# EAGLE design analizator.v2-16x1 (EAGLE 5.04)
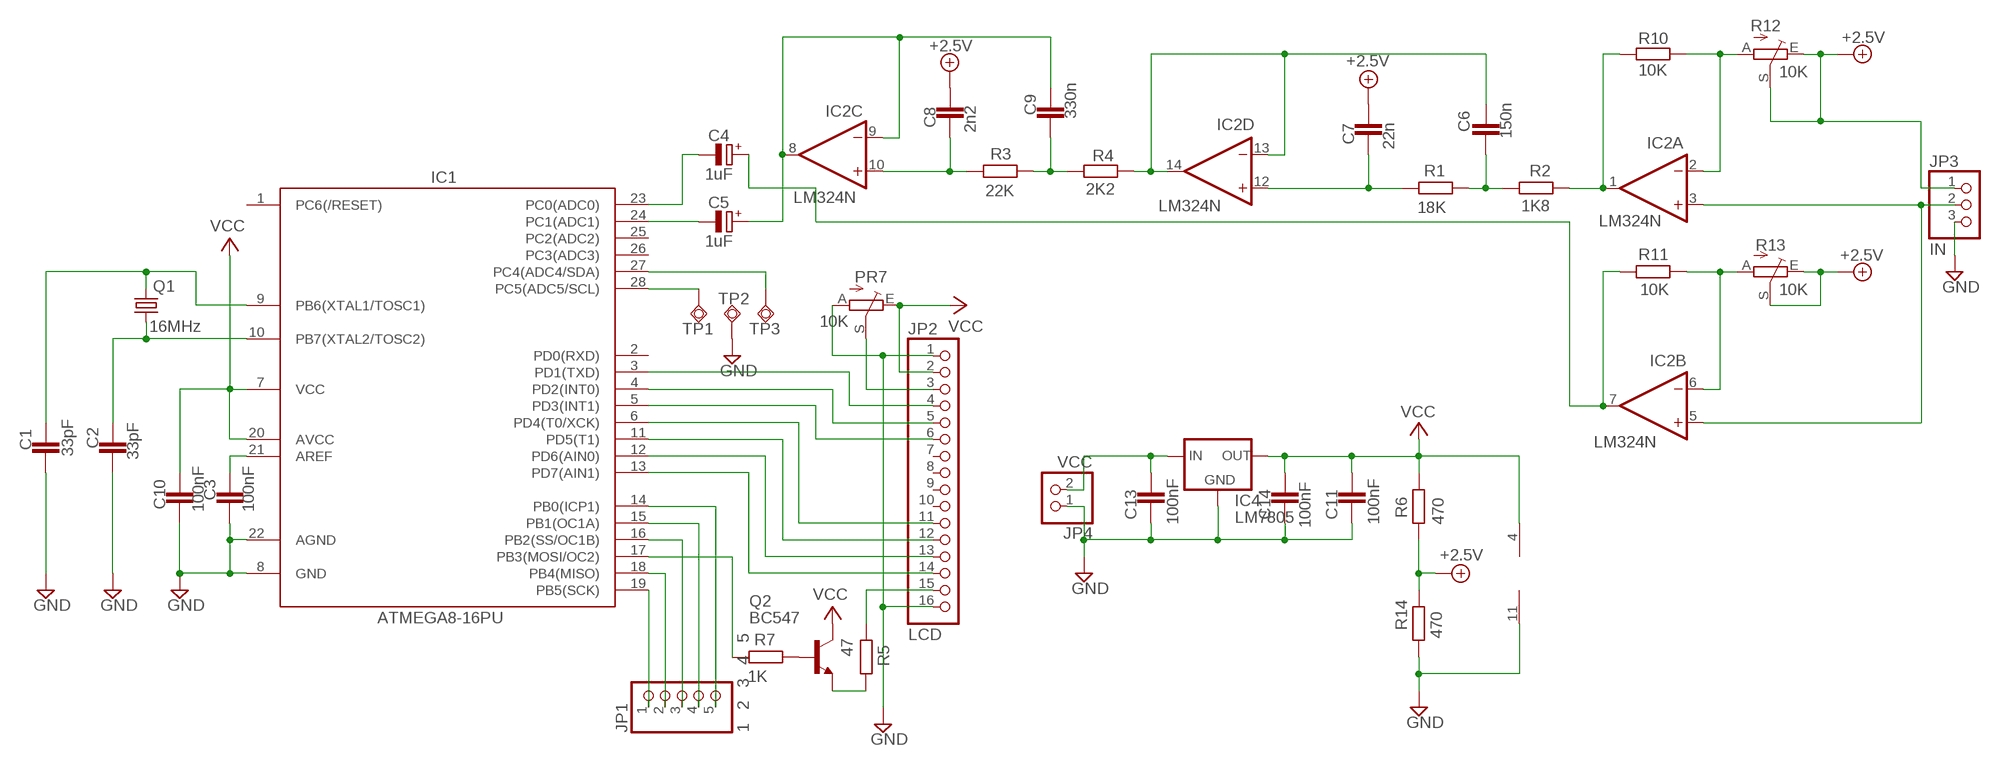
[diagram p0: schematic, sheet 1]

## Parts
C1  33pF  C-EU025-024X044  [C025-024X044]
C2  33pF  C-EU025-024X044  [C025-024X044]
C3  100nF  C-EU050-025X075  [C050-025X075]
C4  1uF  CPOL-EUE5-4  [E5-4]
C5  1uF  CPOL-EUE5-4  [E5-4]
C6  150n  C-EU050-025X075  [C050-025X075]
C7  22n  C-EU050-025X075  [C050-025X075]
C8  2n2  C-EU050-025X075  [C050-025X075]
C9  330n  C-EU050-025X075  [C050-025X075]
C10  100nF  C-EU050-025X075  [C050-025X075]
C11  100nF  C-EU050-025X075  [C050-025X075]
C13  100nF  C-EU050-025X075  [C050-025X075]
C14  100nF  C-EU050-025X075  [C050-025X075]
IC1  ATMEGA8-16PU  ATMEGA8-PU  [DIL28-3]
IC2  LM324N  [DIL14]
IC4  LM7805  78XXL  [78XXL]
JP1  1 2 3 4 5  PINHD-1X5  [1X05]
JP2  LCD  PINHD-1X16  [1X16]
JP3  IN  PINHD-1X3  [1X03]
JP4  VCC  PINHD-1X2  [1X02]
PR7  10K  TRIM_EU-CA6V  [CA6V]
Q1  16MHz  CRYTALHC49S  [HC49/S]
Q2  BC547  [TO92]
R1  18K  R-EU_0204/7  [0204/7]
R2  1K8  R-EU_0204/7  [0204/7]
R3  22K  R-EU_0204/7  [0204/7]
R4  2K2  R-EU_0204/7  [0204/7]
R5  47  R-EU_0204/7  [0204/7]
R6  470  R-EU_0204/7  [0204/7]
R7  1K  R-EU_0204/7  [0204/7]
R10  10K  R-EU_0204/7  [0204/7]
R11  10K  R-EU_0204/7  [0204/7]
R12  10K  TRIM_EU-CA6V  [CA6V]
R13  10K  TRIM_EU-CA6V  [CA6V]
R14  470  R-EU_0204/7  [0204/7]
TP1  TPSQTP11SQ  [TP11SQ]
TP2  TPSQTP11SQ  [TP11SQ]
TP3  TPSQTP11SQ  [TP11SQ]

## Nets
+5V: C7.1 C8.1 JP3.1 R6.1 R12.E R12.S R13.E R13.S R14.2 ; supply symbol labelled +2.5V
GND: C1.1 C2.1 C3.1 C10.1 C11.2 C13.2 C14.2 IC1.8(GND) IC1.22(AGND) IC2.11(P:V-) IC4.GND JP2.1 JP2.16 JP3.3 JP4.1 PR7.A R14.1 TP2.TP
N$1: C1.2 IC1.9(PB6(XTAL1/TOSC1)) Q1.2
N$2: C2.2 IC1.10(PB7(XTAL2/TOSC2)) Q1.1
N$3: C4.- IC1.23(PC0(ADC0))
N$4: C3.2 IC1.21(AREF)
N$5: C5.- IC1.24(PC1(ADC1))
N$6: C6.2 IC2.13(D:-IN) IC2.14(D:OUT) R4.2
N$7: C5.+ C9.2 IC2.8(C:OUT) IC2.9(C:-IN)
N$8: JP2.3 PR7.S
N$9: C7.2 IC2.12(D:+IN) R1.1
N$10: C6.1 R1.2 R2.1
N$11: IC1.3(PD1(TXD)) JP2.4
N$12: C8.2 IC2.10(C:+IN) R3.1
N$13: C9.1 R3.2 R4.1
N$14: IC1.4(PD2(INT0)) JP2.5
N$15: IC2.2(A:-IN) R10.2 R12.A
N$16: IC2.6(B:-IN) R11.2 R13.A
N$17: IC1.5(PD3(INT1)) JP2.6
N$18: IC1.6(PD4(T0/XCK)) JP2.11
N$19: IC1.11(PD5(T1)) JP2.12
N$20: IC1.12(PD6(AIN0)) JP2.13
N$21: IC1.13(PD7(AIN1)) JP2.14
N$22: IC1.17(PB3(MOSI/OC2)) R7.1
N$23: Q2.1(E) R5.2
N$24: IC2.3(A:+IN) IC2.5(B:+IN) JP3.2
N$25: Q2.2(B) R7.2
N$26: IC2.1(A:OUT) R2.2 R10.1
N$27: C4.+ IC2.7(B:OUT) R11.1
N$28: IC1.19(PB5(SCK)) JP1.1
N$29: JP2.15 R5.1
N$30: IC1.18(PB4(MISO)) JP1.2
N$31: IC1.16(PB2(SS/OC1B)) JP1.3
N$32: IC1.15(PB1(OC1A)) JP1.4
N$33: IC1.28(PC5(ADC5/SCL)) TP1.TP
N$38: IC1.14(PB0(ICP1)) JP1.5
N$39: IC1.27(PC4(ADC4/SDA)) TP3.TP
NS$28: C13.1 IC4.IN JP4.2
VCC: C10.2 C11.1 C14.1 IC1.7(VCC) IC1.20(AVCC) IC2.4(P:V+) IC4.OUT JP2.2 PR7.E Q2.3(C) R6.2
Unconnected: IC1.1(PC6(/RESET)) IC1.2(PD0(RXD)) IC1.25(PC2(ADC2)) IC1.26(PC3(ADC3)) JP2.7 JP2.8 JP2.9 JP2.10

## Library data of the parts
C1-C3 C6-C11 C13 C14 = rcl:C-EU: CAPACITOR, European symbol
C4 C5 = rcl:CPOL-EU: POLARIZED CAPACITOR, European symbol
IC1 = atmega8:ATMEGA8-PU
IC2 = linear:LM324: OP AMP
IC4 = v-reg:78XXL: VOLTAGE REGULATOR
JP1 = pinhead:PINHD-1X5: PIN HEADER
JP2 = pinhead:PINHD-1X16: PIN HEADER
JP3 = pinhead:PINHD-1X3: PIN HEADER
JP4 = pinhead:PINHD-1X2: PIN HEADER
PR7 R12 R13 = pot:TRIM_EU-: POTENTIOMETER
Q1 = crystal:CRYTAL: CRYSTAL
Q2 = transistor-npn:BC547*: NPN Transistor
R1-R7 R10 R11 R14 = rcl:R-EU_: RESISTOR, European symbol
TP1-TP3 = testpad:TPSQ

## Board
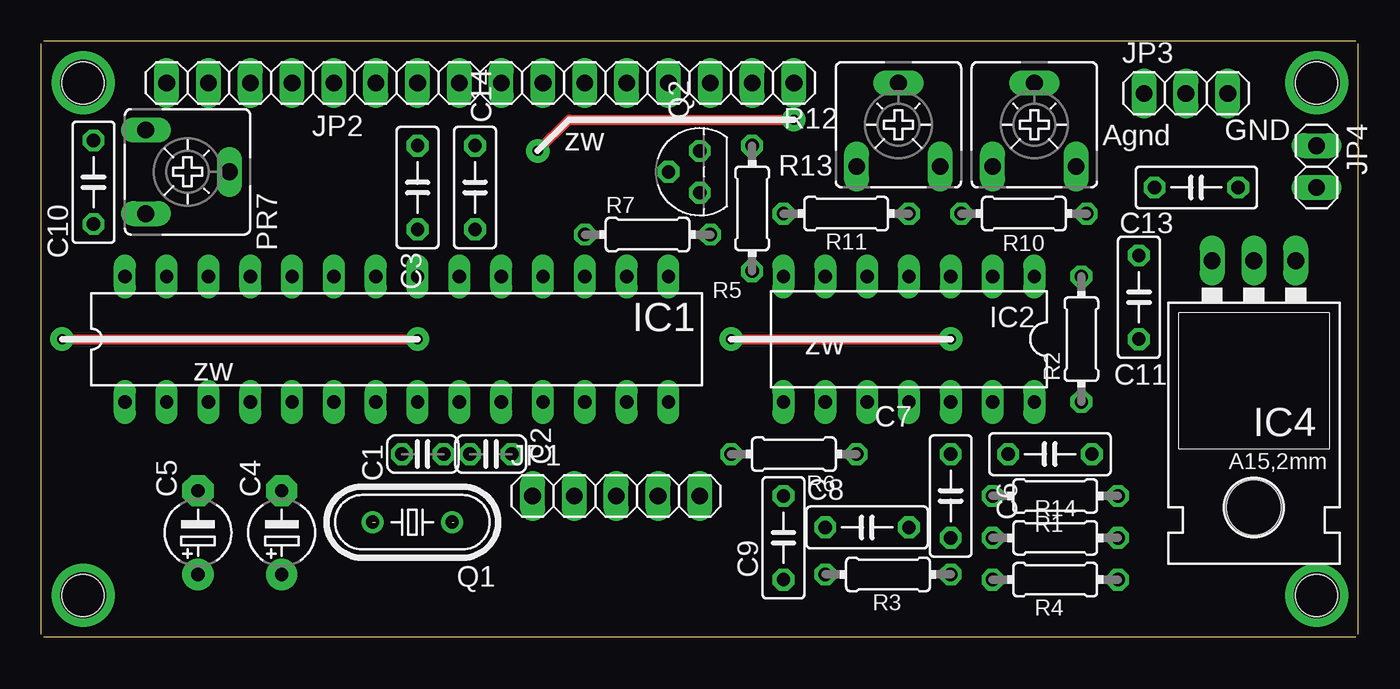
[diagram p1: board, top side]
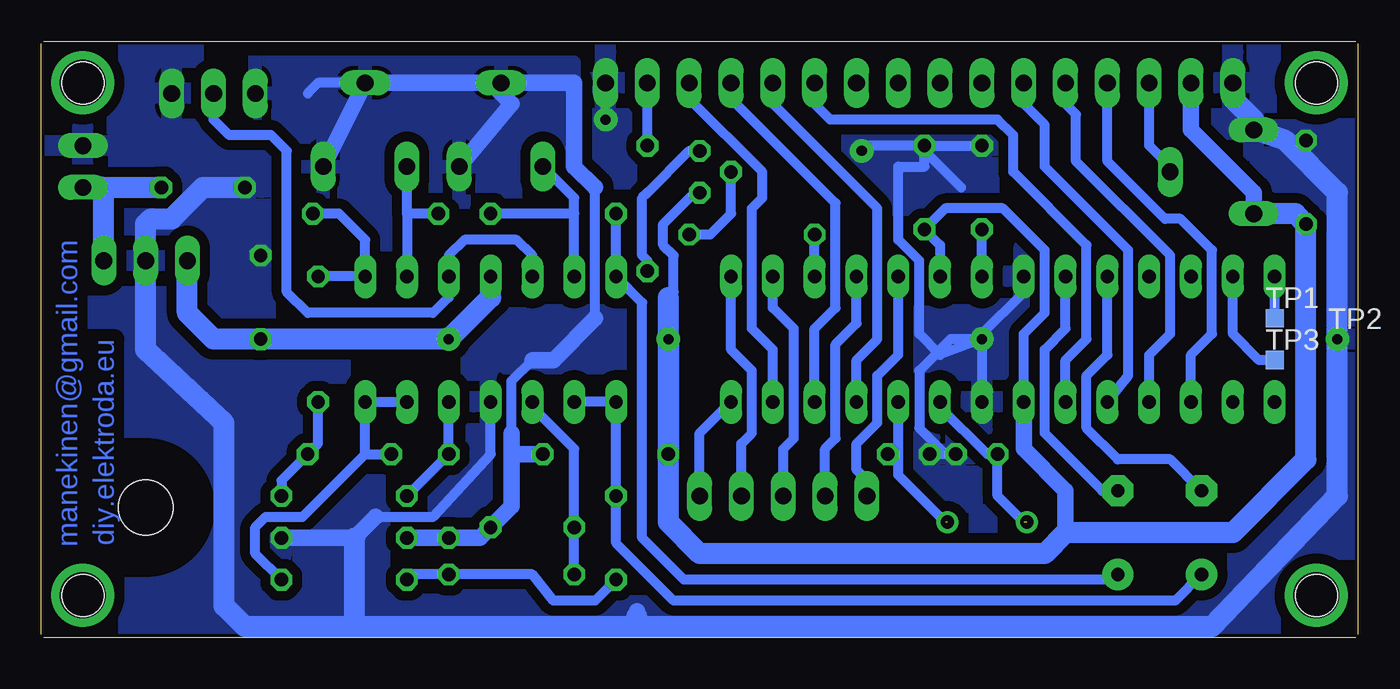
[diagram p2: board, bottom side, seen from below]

Size 80.01 x 36.2 mm. Coordinates in mm from the lower left corner, seen from the top.
Outline: 0,0.17 0,36.04
Outline: 79.85,36.2 0.17,36.2
Outline: 79.85,0 0.17,0
Outline: 80.01,0.17 80.01,36.04
Copper layers (1*16): Top 0.035mm / dielectric 1.5mm / Bottom 0.035mm
Design rules "default *": minimum track width 10mil, minimum drill 24mil, track to track 24mil, track to pad 24mil, pad to pad 24mil, via to via 24mil, smd to smd 24mil, copper to edge 8mil, drill to drill 8mil, minimum pad ring 10mil, minimum via ring 8mil, stop-mask expansion 4mil, vias tented up to drill 0mil, thermal gap 10mil
Holes 2.54 mm at 2.54,33.66 2.54,2.55 77.47,2.55 77.47,33.66

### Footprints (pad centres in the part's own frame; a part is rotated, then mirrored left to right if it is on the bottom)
C025-024X044 = drill 0.813 octagon: 1 -1.27,0; 2 1.27,0
C050-025X075 = drill 0.813 octagon: 1 -2.54,0; 2 2.54,0
E5-4 = drill 0.813 pad 1.905 round: + -2.54,0 | drill 0.813 pad 1.905 octagon: - 2.54,0
DIL28-3 = drill 0.813 long: 1 -16.51,-3.81; 2 -13.97,-3.81; 3 -11.43,-3.81; 4 -8.89,-3.81; 5 -6.35,-3.81; 6 -3.81,-3.81; 7 -1.27,-3.81; 8 1.27,-3.81; 9 3.81,-3.81; 10 6.35,-3.81; 11 8.89,-3.81; 12 11.43,-3.81; 13 13.97,-3.81; 14 16.51,-3.81; 15 16.51,3.81; 16 13.97,3.81; 17 11.43,3.81; 18 8.89,3.81; 19 6.35,3.81; 20 3.81,3.81; 21 1.27,3.81; 22 -1.27,3.81; 23 -3.81,3.81; 24 -6.35,3.81; 25 -8.89,3.81; 26 -11.43,3.81; 27 -13.97,3.81; 28 -16.51,3.81
DIL14 = drill 0.813 long: 1 -7.62,-3.81; 2 -5.08,-3.81; 3 -2.54,-3.81; 4 0,-3.81; 5 2.54,-3.81; 6 5.08,-3.81; 7 7.62,-3.81; 8 7.62,3.81; 9 5.08,3.81; 10 2.54,3.81; 11 0,3.81; 12 -2.54,3.81; 13 -5.08,3.81; 14 -7.62,3.81
78XXL = drill 1.016 long: GND 0,-3.81; IN -2.54,-3.81; OUT 2.54,-3.81 | hole 3.302: 0,11.176
1X05 = drill 1.016 long: 1 -5.08,0; 2 -2.54,0; 3 0,0; 4 2.54,0; 5 5.08,0
1X16 = drill 1.016 long: 1 -19.05,0; 2 -16.51,0; 3 -13.97,0; 4 -11.43,0; 5 -8.89,0; 6 -6.35,0; 7 -3.81,0; 8 -1.27,0; 9 1.27,0; 10 3.81,0; 11 6.35,0; 12 8.89,0; 13 11.43,0; 14 13.97,0; 15 16.51,0; 16 19.05,0
1X03 = drill 1.016 long: 1 -2.54,0; 2 0,0; 3 2.54,0
1X02 = drill 1.016 long: 1 -1.27,0; 2 1.27,0
CA6V = drill 1.016 long: A -2.54,-2.54; E 2.54,-2.54; S 0,2.54
HC49/S = drill 0.813 round: 1 -2.413,0; 2 2.413,0
TO92 = drill 0.813 octagon: 1 1.27,0; 2 0,1.905; 3 -1.27,0
0204/7 = drill 0.813 octagon: 1 -3.81,0; 2 3.81,0
TP11SQ = smd 1.1 x 1.1: TP 0,0

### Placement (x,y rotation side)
C1  23.18,11.12 180 top
C2  27.31,11.12 0 top
C3  22.86,27.31 270 top
C4  14.61,6.36 90 top
C5  9.53,6.36 90 top
C6  61.28,11.12 180 top
C7  55.25,8.58 90 top
C8  50.17,6.67 180 top
C9  45.09,6.04 90 top
C10  3.18,27.63 270 top
C11  66.68,20.64 90 top
C13  70.17,27.31 180 top
C14  26.36,27.31 90 top
IC1  21.59,18.1 0 top
IC2  52.71,18.1 180 top
IC4  73.67,19.05 180 top
JP1  34.93,8.58 0 top
JP2  26.68,33.66 0 top
JP3  69.54,33.02 0 top
JP4  77.47,28.58 270 top
PR7  8.89,28.26 270 top
Q1  22.55,6.99 180 top
Q2  40.01,28.26 90 top
R1  61.6,8.58 0 top
R2  63.19,18.1 90 top
R3  51.44,3.81 0 top
R4  61.6,3.5 0 top
R5  43.19,26.04 270 top
R6  45.73,11.12 180 top
R7  36.84,24.45 0 top
R10  59.7,25.72 180 top
R11  48.9,25.72 0 top
R12  60.33,31.12 0 top
R13  52.08,31.12 0 top
R14  61.6,6.04 180 top
TP1  5.08,19.37 0 bottom
TP2  1.28,18.1 0 bottom
TP3  5.08,16.83 0 bottom

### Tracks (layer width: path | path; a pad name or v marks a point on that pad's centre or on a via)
+5V
  Bottom 0.61: 46.36,19.37 46.36,27.31 | 50.17,16.83 51.44,15.56 51.44,12.39 | R12.S 63.19,33.66 63.82,33.02
  Bottom 1.016: 52.71,33.66 R13.S 47.63,33.66 47.63,28.58 46.36,27.31 | 52.71,33.66 R12.S R12.E | R13.E 51.44,32.39 52.71,33.66 | 46.36,19.37 48.9,16.83 50.17,16.83 | 51.44,11.12 51.44,7.94 C8.1 53.34,6.04 C7.1 R14.2 | 51.44,11.12 51.44,12.39 | 51.44,11.12 R6.1
  pour Bottom: 44.45,20.64 53.98,20.64 53.98,15.56 44.45,15.56
  pour Bottom: 67.31,34.93 64.78,20.64 47.63,20.64 47.63,34.93
GND  (via drill 0.61 pad 1.42)
  Top 0.61: v30.17,29.53 32.07,31.44 v45.73,31.44 | TP2.TP v22.86,18.1
  Bottom 0.61: 24.13,27.31 26.68,29.85 C14.2 | IC1.22 20.32,20.96 22.86,18.42 v22.86,18.1 | v22.86,18.1 IC1.8 | C14.2 C3.1 C14.2 | C14.2 29.85,29.85 v30.17,29.53 | v45.73,31.44 JP2.16 | IC2.11 52.71,11.12 56.2,7.31 59.7,7.31 | v22.86,18.1 25.41,17.15 26.68,18.42 26.68,22.87 27.95,24.14 27.95,28.58 26.36,28.58 C14.2 | v22.86,18.1 24.77,18.1 26.68,16.2 26.68,12.71 25.09,11.12 | 25.09,11.12 C2.1 | 25.09,11.12 C1.1
  Bottom 1.016: 59.7,7.31 60.96,6.04 R14.1 | 43.82,1.27 43.82,1.59
  Bottom 1.27: JP2.1 7.63,32.71 6.36,31.44 PR7.A 4.45,30.17 1.28,26.99 TP2.TP 1.28,8.58 8.89,0.64 43.82,0.64 | 43.82,0.64 43.82,1.27 | 43.82,0.64 60.96,0.64 | 60.96,0.64 67.63,0.64 68.9,1.91 68.9,13.02 73.67,17.47 73.67,25.09 73.35,25.41 72.08,25.41 70.17,27.31 C13.2 | 60.96,0.64 60.96,6.04
  other vias: 1.28,18.1
  pour Bottom: -0.63,35.88 -0.63,0.32 80.02,0.32 80.02,35.88
N$1  (1 unrouted)
  Bottom 0.61: IC1.9 25.41,13.97 22.55,11.12 C1.2 21.91,8.58 20.32,6.99
N$2  (1 unrouted)
  Bottom 0.61: 27.95,11.12 IC1.10 | 27.95,11.12 C2.2 | 27.95,11.12 27.95,9.85 25.09,6.99
N$3
  Bottom 0.61: IC1.23 17.79,18.74 19.05,17.47 19.05,12.39 15.56,8.89 C4.-
N$4
  Bottom 0.61: IC1.21 C3.2
N$5
  Bottom 0.61: IC1.24 15.25,17.15 16.52,15.88 16.52,12.71 14.61,10.8 11.43,10.8 C5.-
N$6
  Bottom 0.61: R4.2 67,5.09 67,6.67 66.36,7.31 64.14,7.31 60.33,11.12 | IC2.13 IC2.14 60.33,11.12 | 60.33,11.12 C6.2
N$7
  Bottom 0.61: C5.+ 11.12,2.23 41.6,2.23 45.09,5.72 C9.2 IC2.8 IC2.9
N$8
  Bottom 0.61: PR7.S 11.43,28.58 12.71,29.85 JP2.3
N$9
  Bottom 0.61: IC2.12 C7.2 R1.1
N$10
  Bottom 0.61: 63.19,13.66 R2.1 63.19,11.75 C6.1 65.41,9.53 R1.2
N$11
  Bottom 0.61: IC1.3 10.16,17.15 8.89,18.42 8.89,23.5 10.8,25.41 11.75,25.41 15.25,28.9 JP2.4
N$12
  Bottom 0.61: IC2.10 50.17,13.97 47.63,11.44 C8.2 R3.1
N$13
  Bottom 0.61: C9.1 46.36,2.23 48.9,2.23 50.17,3.81 R3.2 57.16,3.81 57.47,3.81 R4.1
N$14
  Bottom 0.61: IC1.4 12.71,17.15 11.43,18.42 11.43,23.18 17.15,28.9 17.15,31.76 17.79,32.39 JP2.5
N$15
  Bottom 0.61: 57.79,25.72 IC2.2 | 57.79,25.72 R12.A | R10.2 57.79,25.72
N$16
  Bottom 0.61: IC2.6 47.63,25.72 | 47.63,25.72 47.63,26.68 R13.A | 47.63,25.72 R11.2
N$17
  Bottom 0.61: IC1.5 13.97,15.88 13.97,23.5 19.05,28.58 19.05,31.12 20.32,32.39 JP2.6
N$18
  Bottom 0.61: IC1.6 17.79,16.83 16.52,18.1 16.52,23.82 20.96,28.26 20.96,30.48 21.91,31.44 32.07,31.44 33.02,32.39 JP2.11
N$19
  Bottom 0.61: IC1.11 30.48,16.83 29.21,18.1 29.21,26.04 35.56,32.39 JP2.12
N$20
  Bottom 0.61: IC1.12 33.02,18.74 31.76,20.01 31.76,26.36 38.1,32.71 JP2.13
N$21
  Bottom 0.61: IC1.13 35.56,17.47 36.84,18.74 36.84,26.04 36.2,26.68 36.2,28.26 40.64,32.71 JP2.14
N$22
  Bottom 0.61: IC1.17 R7.1
N$23
  Bottom 0.61: R5.2 43.19,22.87 43.5,23.18 43.5,26.68 43.19,26.99 40.64,29.53 Q2.1
N$24
  Bottom 0.61: IC2.5 50.17,23.18 51.12,24.14 54.3,24.14 55.25,23.18 IC2.3 55.25,20.64 56.2,19.69 63.82,19.69 65.09,20.96 65.09,29.53 66.05,30.48 68.58,30.48 69.54,31.44 JP3.2
N$25
  Bottom 0.61: R7.2 39.38,24.45 38.1,25.72 Q2.2
N$26
  Bottom 0.61: R2.2 IC2.1 60.33,24.14 61.92,25.72 R10.1
N$27
  Bottom 0.61: C4.+ 14.93,3.5 40.96,3.5 43.5,6.04 43.5,20.33 IC2.7 R11.1
N$28
  Bottom 0.61: IC1.19 27.95,17.15 29.21,15.88 29.21,13.02 30.48,11.75 30.48,10.16 29.85,9.53 JP1.1
N$29
  Bottom 0.61: R5.1 JP2.15
N$30
  Bottom 0.61: IC1.18 30.48,19.05 31.76,17.79 31.76,12.07 32.39,11.44 JP1.2
N$31
  Bottom 0.61: IC1.16 35.56,20.01 34.3,18.74 34.3,12.07 34.93,11.44 JP1.3
N$32
  Bottom 0.61: IC1.15 38.1,17.47 36.84,16.2 36.84,12.39 37.47,11.75 JP1.4
N$33
  Bottom 0.61: TP1.TP IC1.28
N$34  (via drill 2.8 pad 2.54)
  other vias: 2.54,33.66
N$35  (via drill 2.8 pad 2.54)
  other vias: 77.47,33.66
N$36  (via drill 2.8 pad 2.54)
  other vias: 2.54,2.55
N$37  (via drill 2.8 pad 2.54)
  other vias: 77.47,2.55
N$38
  Bottom 0.61: IC1.14 40.01,12.39 JP1.5
N$39
  Bottom 0.61: TP3.TP 6.04,16.83 7.63,18.42 IC1.27
NS$28
  Bottom 1.27: 76.2,27.31 C13.1 | 76.2,27.31 JP4.2 | IC4.IN 76.2,27.31
VCC  (via drill 0.61 pad 1.42)
  Top 0.61: v41.91,18.1 v55.25,18.1
  Bottom 0.61: IC1.20 25.41,23.82 C14.1 25.09,26.04 21.59,26.04 19.05,23.5 19.05,19.69 20.32,18.42 IC1.7 | Q2.3 40.33,26.99 42.23,25.09 42.23,23.82 41.6,23.18 41.6,20.96 41.91,20.64
  Bottom 1.016: PR7.E 6.36,26.99 10.16,30.8 JP2.2 | 17.79,6.36 17.79,8.89 20.32,11.44 IC1.7
  Bottom 1.27: PR7.E 3.82,25.72 C10.2 3.18,10.8 7.63,6.36 17.79,6.36 19.05,5.09 40.01,5.09 41.91,6.99 v41.91,18.1 | IC2.4 52.71,20.64 v55.25,18.1 C11.1 69.54,18.1 71.12,19.69 IC4.OUT | v41.91,18.1 R6.2 | v41.91,18.1 41.91,20.64

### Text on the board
Bottom: manekinen@gmail.com | diy.elektroda.eu
tPlace: GND | Agnd | zw | zw | zw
